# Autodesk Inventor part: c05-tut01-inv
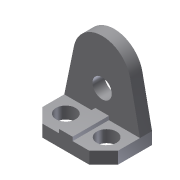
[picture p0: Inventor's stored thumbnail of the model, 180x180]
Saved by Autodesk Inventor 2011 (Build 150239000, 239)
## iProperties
Created: 2010-02
Part Number: c05-tut01-inv
Document SubType Name: Modeling
Designer: CADSoft
Density: 1 g/cm^3
Author: CADSoft
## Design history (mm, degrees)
sketch "Sketch1"
  geometry: L1 (-200, 0)-(0, 0); L2 (0, 0)-(0, -90); L3 (-38, -128)-(-162, -128); L4 (-200, -90)-(-200, 0); L5 (-200, -90)-(-162, -128); L6 (0, -90)-(-38, -128); C1 r 26 at (-154, -74); C2 r 26 at (-46, -74); 2 further points
  constraints: 12 end point, 2 centre point, 2 coincident, 2 equal length, 2 vertical, 1 equal radius, 1 horizontal, 1 horizontal alignment, 1 other
  dimensions: "d0" = 90 distance of L4.start L1.start; "d1" = 128 distance between parallel lines of L3 L1; "d2" = 38 horizontal distance of L4.start L3.end; "d3" = 124 distance of L3.start L3.end; "d4" = 52 diameter of C2; "d5" = 46 distance from line of L2 C2.centre; "d6" = 74 distance from line of L1 C2.centre; "d8" = 46 distance from line of L4 C1.centre
extrude "Extrusion1" new body sketch "Sketch1" distance "d9" = 32; taper "d10" = 0 deg
sketch "Sketch2"
  geometry: L1 (0, -32)-(200, -32) reference; L2 (200, -32)-(174.418, -155.424); L3 (25.582, -155.424)-(0, -32); C1 r 25.5 at (100, -96); A1 r 76 centre (100, -140) between (25.582, -155.424) and (174.418, -155.424)
  constraints: 4 end point, 2 centre point, 2 point on circle, 2 tangent, 1 equal length, 1 vertical alignment
  dimensions: "d11" = 76 radius of A1; "d12" = 108 distance from line of L1 A1.centre; "d13" = 51 diameter of C1; "d14" = 64 distance from line of L1 C1.centre
extrude "Extrusion2" join sketch "Sketch2" distance "d15" = 32; taper "d16" = 0 deg
sketch "Sketch3"
  geometry: L1 (44, 42)-(80, 42); L2 (80, 42)-(80, 32); L3 (80, 32)-(44, 32); L4 (44, 32)-(44, 42); L5 (-38, 0)-(-38, 32) reference; L6 (124, 32)-(0, 32) reference
  constraints: 8 end point, 2 horizontal, 2 vertical, 1 collinear
  dimensions: "d17" = 10 distance of L3.end L1.start; "d18" = 36 distance of L1.start L1.end; "d19" = 82 distance between parallel lines of L4 L5
extrude "Extrusion4" join sketch "Sketch3" stored distance "d22" = 10; taper "d23" = 0 deg
body "Solid1"
